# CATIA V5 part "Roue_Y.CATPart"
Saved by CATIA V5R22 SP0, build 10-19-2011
Part number: Roue_Y
Material "Antidérapant"
Bounding box of the stored display mesh (mm): x -12 to 12, y -11.818 to 11.818, z 0 to 23
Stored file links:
  U:\S9A\PER\CAO_Projet_ZG4\Cadre\Chariot_Y\Roue_Y.CATPart
  U:\S9A\PER\CAO_Projet_ZG4\Cadre\Chariot_Y\no_skid.jpg
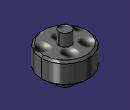
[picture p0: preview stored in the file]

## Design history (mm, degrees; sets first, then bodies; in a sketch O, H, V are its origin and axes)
Body1 (main body), material "Antidérapant"
  Sketch1 on xy-plane, origin (0, 0, 0), H (1, 0, 0), V (0, 1, 0)
    circle A1 centre (0, 0) radius 4
    radius A1 = 4
  Pad1: profile Sketch1, direction (0, 0, 1), length 6
  Sketch2 on end face of Pad1, origin (0, 0, 6), H (1, 0, 0), V (0, 1, 0)
    circle A1 centre (0, 0) radius 12
    radius A1 = 12
  Pad2: profile Sketch2, direction (0, 0, 1), length 11
  Sketch3 on end face of Pad2, origin (0, 0, 17), H (1, 0, 0), V (0, 1, 0)
    circle A1 centre (0, 0) radius 3
    radius A1 = 3
  Pad3: profile Sketch3, direction (0, 0, 1), length 6
  Chamfer1: length 1, angle 45, on edge [face of Pad2 from Sketch2.A1 | end face of Pad2]; edge [start face of Pad2 | face of Pad2 from Sketch2.A1]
